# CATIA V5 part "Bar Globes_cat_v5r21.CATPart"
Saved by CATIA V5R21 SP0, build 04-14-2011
Part number: Bar Globes
Bounding box of the stored display mesh (mm): x -5.943 to 5.967, y -4.926 to 5, z -5.848 to 5.999
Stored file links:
  D:\CATIA V5R21 E-RESOURCES\CATIA-V5R21\catia-v5r21-Tut\c13-catia-v5r21-tut\c13-catia-v5r21-tut02\Bench Vice\Bar Globes_cat_v5r21.CATPart
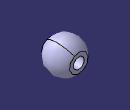
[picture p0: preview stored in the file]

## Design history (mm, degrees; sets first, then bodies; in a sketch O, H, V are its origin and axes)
Body1 (main body)
  Sketch1 on yz-plane, origin (0, 0, 0), H (0, 1, 0), V (0, 0, 1)
    arc A1 centre (0, 0) radius 6 from (6, 0) to (-6, 0) ccw
    line L1 (-6, 0) -> (6, 0)
    radius A1 = 6
    horizontal: L1 H
    coincidence: H L1
  Shaft1: profile Sketch1, axis edge of Sketch1, angle 360
  Sketch2 on yz-plane, origin (0, 0, 0), H (0, 1, 0), V (0, 0, 1)
    line L1 (-5, 7.2498) -> (5, 7.2498)
    line L2 (5, 7.2498) -> (5, -8.5554)
    line L3 (5, -8.5554) -> (1.27, -8.5554)
    line L4 (-5, -8.5554) -> (-5, 7.2498)
    line L5 (1.27, -8.5554) -> (1.27, -9.941)
    line L6 (1.27, -9.941) -> (8.2768, -9.941)
    line L7 (8.2768, -9.941) -> (8.2768, 9.8096)
    line L8 (8.2768, 9.8096) -> (-8.9775, 9.8096)
    line L9 (-8.9775, 9.8096) -> (-8.9775, -10.3789)
    line L10 (-8.9775, -10.3789) -> (-2.0145, -10.3789)
    line L11 (-2.0145, -10.3789) -> (-2.0145, -8.5554)
    point P12 (-2.0145, -8.5554)
    line L12 (-2.0145, -8.5554) -> (-5, -8.5554)
    length L1 = 10
    distance V L4 = 5
    horizontal: L1 H, L3 H, L6 H, L8 H, L10 H, L12 H
    vertical: L2 V, L4 V, L5 V, L7 V, L9 V, L11 V
    coincidence: P12 L3, L3 L12
  Pocket1: profile Sketch2, direction (-1, 0, 0), length 20, mirrored extent
  Sketch3 on face of Pocket1, origin (0.8583, -5, 1.5686), H (1, 0, 0), V (0, 0, 1)
    point P1 (-0.8583, -1.5686)
    reference intersected line E1 through (0, -1.5686) direction (-1, 0) from xy-plane
    reference intersected line E2 through (-0.8583, 0) direction (0, 1) from yz-plane
    coincidence: P1 E1, E2 P1
  Hole1: placed by Sketch3, at (0, -5, 0) direction (0, 1, 0), diameter 4, depth 10, countersink depth 1.5, countersink angle 90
